// Mitsubishi GX Works2 project: 430-H3G参考例程   PLC: FX3G

PROGRAM MAIN
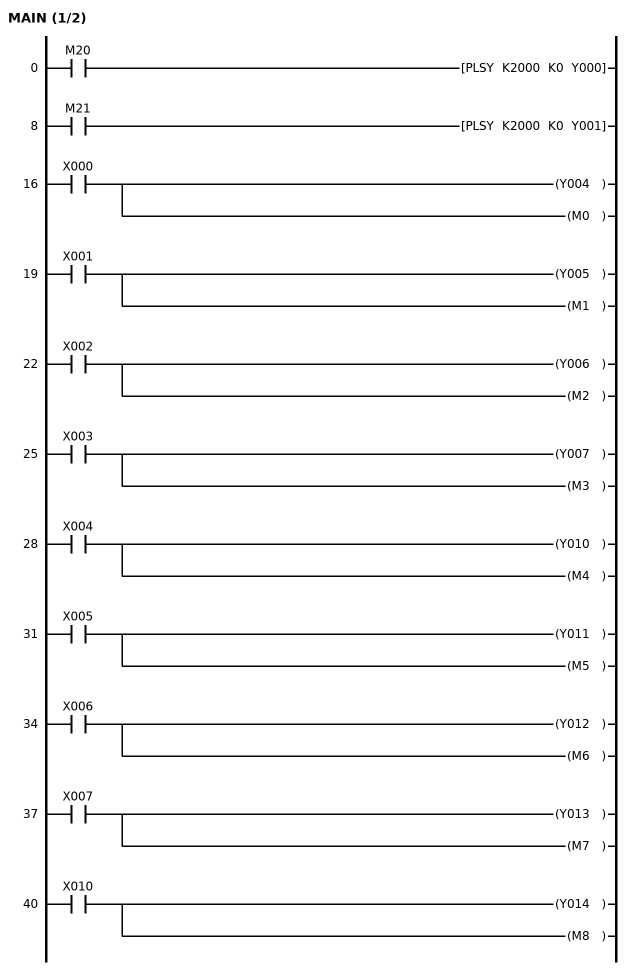
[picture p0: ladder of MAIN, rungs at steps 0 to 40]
0     LD      M20
      PLSY    K2000 K0 Y000
8     LD      M21
      PLSY    K2000 K0 Y001
16    LD      X000
      OUT     Y004
      OUT     M0
19    LD      X001
      OUT     Y005
      OUT     M1
22    LD      X002
      OUT     Y006
      OUT     M2
25    LD      X003
      OUT     Y007
      OUT     M3
28    LD      X004
      OUT     Y010
      OUT     M4
31    LD      X005
      OUT     Y011
      OUT     M5
34    LD      X006
      OUT     Y012
      OUT     M6
37    LD      X007
      OUT     Y013
      OUT     M7
40    LD      X010
      OUT     Y014
      OUT     M8
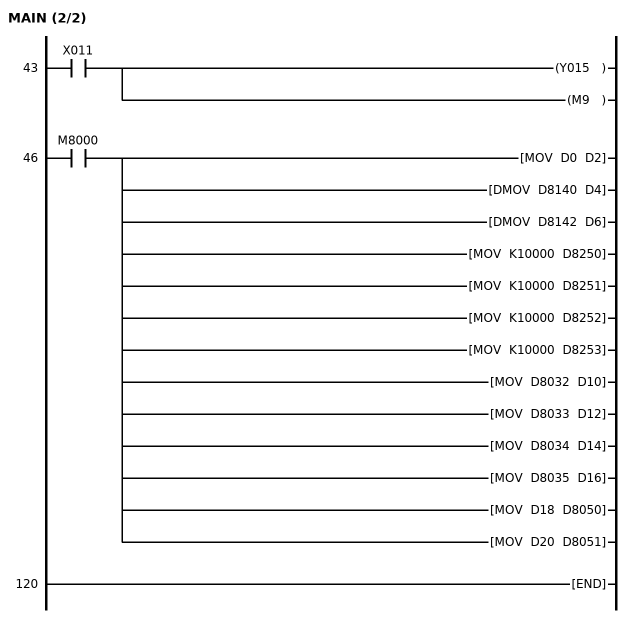
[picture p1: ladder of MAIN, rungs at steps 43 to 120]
43    LD      X011
      OUT     Y015
      OUT     M9
46    LD      M8000
      MOV     D0 D2
      DMOV    D8140 D4
      DMOV    D8142 D6
      MOV     K10000 D8250
      MOV     K10000 D8251
      MOV     K10000 D8252
      MOV     K10000 D8253
      MOV     D8032 D10
      MOV     D8033 D12
      MOV     D8034 D14
      MOV     D8035 D16
      MOV     D18 D8050
      MOV     D20 D8051
120   END
END_PROGRAM
